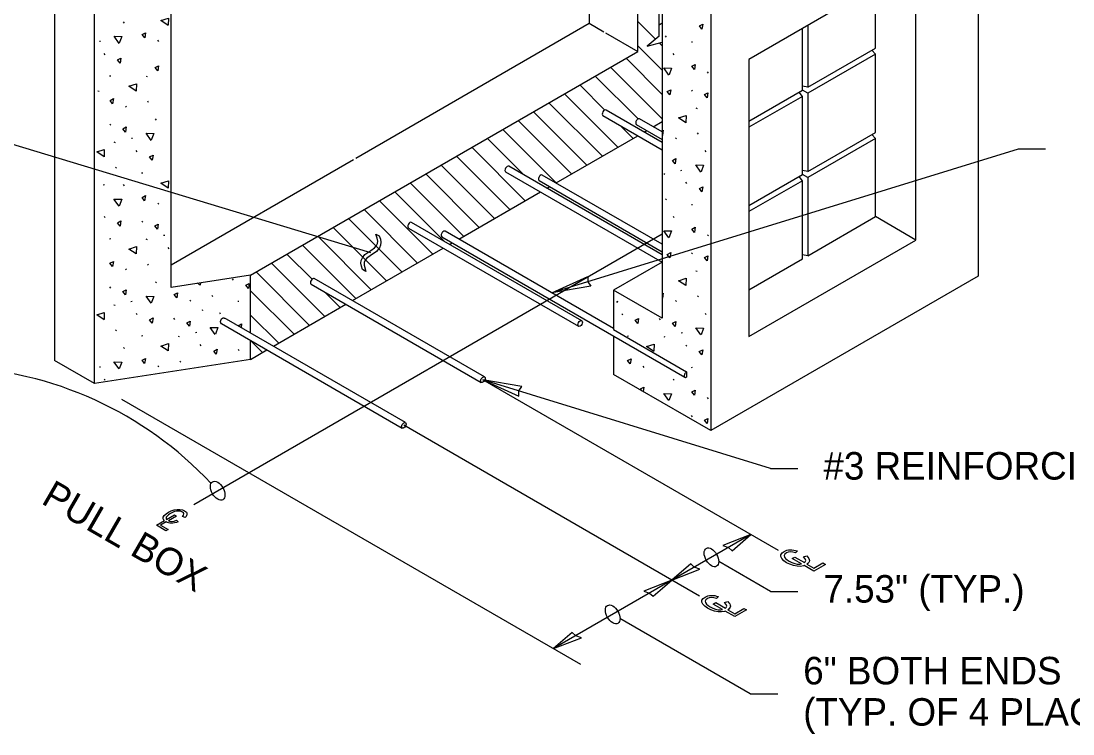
# Model space of a CAD drawing. Extents: x 99862 to 103151, y 100000 to 105076.
# Drawn here: x 100499 to 101110, y 104068 to 104482 of the extents above; entities that cross this region are included whole.
import ezdxf

# ---------------------------------------------------------------- set-up
doc = ezdxf.new("R2010")
doc.units = 0
for name, color, linetype in [('Level 14', 7, 'Continuous'), ('Level 15', 7, 'Continuous'), ('Level 2', 7, 'Continuous'), ('Level 20', 7, 'Continuous'), ('Level 9', 7, 'Continuous')]:
    doc.layers.add(name, color=color, linetype=linetype)

msp = doc.modelspace()

# ---------------------------------------------------------------- linework, layer by layer
at = {"layer": 'Level 14'}
for p, q in [((100871.55, 104411.82), (100838.9, 104430.67)), ((100837.03, 104427.42), (100871.55, 104407.49)), ((100871.55, 104417.94), (100858.35, 104425.57)), ((100856.47, 104422.32), (100871.55, 104413.61)), ((100780.46, 104394.76), (100871.45, 104342.23)), ((100871.55, 104346.5), (100782.33, 104398.01)), ((100799.9, 104389.66), (100871.55, 104348.29)), ((100871.55, 104352.63), (100801.78, 104392.91)), ((100824.76, 104308.2), (100725.77, 104365.35)), ((100723.89, 104362.1), (100822.89, 104304.95)), ((100743.34, 104357), (100884.76, 104275.35)), ((100843.27, 104303.64), (100745.21, 104360.25)), ((100768.19, 104275.54), (100669.2, 104332.69)), ((100667.32, 104329.44), (100766.32, 104272.29)), ((100722.23, 104249), (100618.09, 104309.13)), ((100615.13, 104306.51), (100720.36, 104245.75)), ((100843.27, 104303), (100885.7, 104278.51)), ((100885.7, 104278.51), (100885.7, 104275.44))]:
    msp.add_line(p, q, dxfattribs=at)
for centre, major_axis, start_param, end_param in [((100837.97, 104429.05), (-0.94, -1.62), 3.1416, 6.283185), ((100837.97, 104429.05), (-0.94, -1.62), 3.141593, 3.1416), ((100857.41, 104423.94), (-0.94, -1.62), 3.141593, 6.283191), ((100857.41, 104423.94), (-0.94, -1.62), 3.14158, 3.141593), ((100781.4, 104396.39), (-0.94, -1.62), 3.1416, 6.283185), ((100781.4, 104396.39), (-0.94, -1.62), 3.141593, 3.1416), ((100800.84, 104391.28), (0.94, 1.62), 6.283185, 9.424778), ((100724.83, 104363.73), (-0.94, -1.62), 3.1416, 6.283185), ((100724.83, 104363.73), (-0.94, -1.62), 3.141593, 3.1416), ((100744.27, 104358.62), (0.94, 1.62), 6.283185, 9.424778), ((100668.26, 104331.07), (-0.94, -1.62), 3.1416, 6.283185), ((100668.26, 104331.07), (-0.94, -1.62), 3.141593, 3.1416), ((100885.7, 104276.98), (0.94, 1.62), 0.785398, 3.926991)]:
    msp.add_ellipse(centre, major_axis=major_axis, ratio=0.57735, start_param=start_param, end_param=end_param, dxfattribs=at)
for centre, major_axis in [((100823.82, 104306.57), (-0.94, -1.62)), ((100767.25, 104273.91), (-0.94, -1.62)), ((100721.29, 104247.38), (0.94, 1.62))]:
    msp.add_ellipse(centre, major_axis=major_axis, ratio=0.57735, dxfattribs=at)
msp.add_open_spline([(100618.09, 104309.13), (100616.3, 104310.16), (100614.52, 104308.86), (100614.52, 104307.49), (100614.52, 104307.12), (100614.7, 104306.76), (100615.13, 104306.51)], degree=4, dxfattribs=at)
at = {"layer": 'Level 15'}
for p, q in [((100702.12, 104347.71), (100460.43, 104420.67)), ((101078.52, 104407.97), (100807.38, 104324.36)), ((101094.52, 104407.97), (101078.52, 104407.97)), ((100599.14, 104201.35), (100871.55, 104358.62)), ((100705.79, 104356.24), (100705.05, 104358.55)), ((100705.05, 104358.55), (100706.88, 104357.5)), ((100706.88, 104357.5), (100707.65, 104355.66)), ((100704.16, 104350.49), (100705.41, 104351.94)), ((100705.41, 104351.94), (100705.91, 104353.18)), ((100706.06, 104354.53), (100705.79, 104356.24)), ((100705.91, 104353.18), (100706.06, 104354.53)), ((100707.74, 104352.2), (100707.07, 104350.57)), ((100707.65, 104355.66), (100707.94, 104353.89)), ((100707.94, 104353.89), (100707.74, 104352.2)), ((100696.48, 104343.3), (100697.13, 104344.83)), ((100697.13, 104344.83), (100698.67, 104346.75)), ((100698.67, 104346.75), (100702.07, 104349.02)), ((100701.69, 104345.97), (100699.7, 104344.58)), ((100705.32, 104348.49), (100701.69, 104345.97)), ((100702.07, 104349.02), (100704.16, 104350.49)), ((100707.07, 104350.57), (100705.32, 104348.49)), ((100696.3, 104341.69), (100696.48, 104343.3)), ((100696.57, 104339.93), (100696.3, 104341.69)), ((100697.32, 104337.92), (100696.57, 104339.93)), ((100698.28, 104342.08), (100698.22, 104340.44)), ((100698.22, 104340.44), (100699.15, 104336.86)), ((100698.75, 104343.42), (100698.28, 104342.08)), ((100699.7, 104344.58), (100698.75, 104343.42)), ((100699.15, 104336.86), (100697.32, 104337.92)), ((100939.18, 104174.65), (100767.25, 104273.91)), ((100934.5, 104222.33), (100767.25, 104273.91)), ((100824.27, 104108.31), (100557.32, 104262.44)), ((100893.22, 104148.12), (100721.29, 104247.38)), ((100934.5, 104222.33), (100950.5, 104222.33)), ((100923.18, 104183.89), (100877.22, 104157.35)), ((100934.5, 104150.82), (100904.44, 104168.17)), ((100877.22, 104157.35), (100808.27, 104117.55)), ((100934.5, 104150.82), (100950.5, 104150.82)), ((100922.75, 104091.26), (100846.99, 104135)), ((100922.75, 104091.26), (100938.75, 104091.26))]:
    msp.add_line(p, q, dxfattribs=at)
for points in [[(100807.38, 104324.36), (100828.31, 104333.94), (100828.19, 104330.77), (100830.08, 104328.23)], [(100767.25, 104273.91), (100788.19, 104264.33), (100788.06, 104267.5), (100789.95, 104270.04)], [(100923.18, 104183.89), (100906.89, 104177.57), (100910.19, 104176.39), (100912.23, 104174.48)], [(100877.22, 104157.36), (100893.51, 104163.68), (100890.21, 104164.86), (100888.17, 104166.76)], [(100877.22, 104157.35), (100860.92, 104151.03), (100864.23, 104149.85), (100866.27, 104147.95)], [(100808.27, 104117.55), (100824.57, 104123.87), (100821.27, 104125.05), (100819.22, 104126.96)]]:
    msp.add_lwpolyline(points, close=True, dxfattribs=at)
msp.add_arc((100452.38, 104066.63), 214.86, 43.15406, 87.85248, dxfattribs=at)
for centre in [(100612.99, 104209.35), (100900.2, 104170.62), (100842.75, 104137.45)]:
    msp.add_ellipse(centre, major_axis=(-3, 5.2), ratio=0.57735, dxfattribs=at)
at = {"layer": 'Level 2'}
for p, q in [((101055.4, 104628.07), (101055.4, 104334.13)), ((100518, 104579.08), (100518, 104285.14)), ((100541.32, 104271.68), (100541.32, 104565.61)), ((100585.94, 104447.06), (100585.94, 104568.43)), ((101019.13, 104516.26), (100921.96, 104460.16)), ((101019.13, 104355.07), (101019.13, 104516.26)), ((100829.13, 104512.04), (100829.13, 104481.1)), ((100995.52, 104466.68), (100995.52, 104502.63)), ((100899.84, 104497.43), (100899.84, 104244.32)), ((100857.41, 104464.77), (100857.41, 104490.4)), ((100869.79, 104473.7), (100869.79, 104490.43)), ((100871.55, 104490.29), (100871.55, 104309.64)), ((100693.28, 104402.67), (100829.13, 104481.1)), ((100829.13, 104481.1), (100837.55, 104476.24)), ((100857.41, 104482.18), (100867.66, 104471.94)), ((100871.55, 104481.1), (100869.79, 104480.08)), ((100956.19, 104479.92), (100956.19, 104443.98)), ((100838.64, 104475.61), (100857.41, 104464.77)), ((100869.79, 104473.7), (100862.71, 104467.83)), ((100953.09, 104442.19), (100953.09, 104478.13)), ((100857.41, 104468.04), (100871.55, 104453.9)), ((100862.71, 104467.83), (100871.55, 104470.2)), ((100869.85, 104469.74), (100871.55, 104468.04)), ((100632.15, 104334.72), (100857.41, 104464.77)), ((100956.19, 104443.98), (100995.52, 104466.68)), ((100995.52, 104463.11), (100956.19, 104440.4)), ((100995.52, 104463.11), (100993.53, 104465.54)), ((100995.52, 104417.69), (100995.52, 104463.11)), ((100841.55, 104455.61), (100871.55, 104425.62)), ((100850.52, 104460.79), (100871.55, 104439.76)), ((100921.96, 104460.16), (100921.96, 104298.97)), ((100832.59, 104450.44), (100857.54, 104425.48)), ((100585.94, 104327.57), (100585.94, 104447.06)), ((100823.62, 104445.26), (100838.22, 104430.66)), ((100956.19, 104443.98), (100953.09, 104444.48)), ((100814.66, 104440.09), (100845.72, 104409.03)), ((100921.96, 104424.22), (100953.09, 104442.19)), ((100953.09, 104438.61), (100921.96, 104420.64)), ((100953.09, 104438.61), (100951.11, 104441.04)), ((100956.19, 104440.4), (100953.09, 104442.19)), ((100953.09, 104393.2), (100953.09, 104438.61)), ((100956.19, 104440.4), (100956.19, 104394.99)), ((100805.69, 104434.91), (100836.75, 104403.85)), ((100787.76, 104424.56), (100818.82, 104393.5)), ((100796.73, 104429.73), (100827.78, 104398.67)), ((100778.79, 104419.38), (100809.85, 104388.32)), ((100847.52, 104421.37), (100854.68, 104414.2)), ((100861.05, 104417.88), (100862.61, 104418.78)), ((100866.36, 104420.94), (100871.55, 104423.94)), ((100769.83, 104414.2), (100791.05, 104392.98)), ((100809.79, 104388.28), (100857.3, 104415.72)), ((100956.19, 104394.99), (100995.52, 104417.69)), ((100995.52, 104414.12), (100956.19, 104391.41)), ((100995.52, 104414.12), (100993.53, 104416.55)), ((100995.52, 104368.7), (100995.52, 104414.12)), ((100760.86, 104409.03), (100791.92, 104377.97)), ((100585.94, 104340.69), (100692.06, 104401.97)), ((100751.9, 104403.85), (100782.95, 104372.79)), ((100742.93, 104398.67), (100773.99, 104367.62)), ((100956.19, 104394.99), (100953.09, 104395.49)), ((100725, 104388.32), (100756.06, 104357.26)), ((100733.97, 104393.5), (100765.02, 104362.44)), ((100921.96, 104375.23), (100953.09, 104393.2)), ((100953.09, 104389.62), (100921.96, 104371.65)), ((100953.09, 104389.62), (100951.11, 104392.05)), ((100956.19, 104391.41), (100953.09, 104393.2)), ((100953.09, 104344.21), (100953.09, 104389.62)), ((100956.19, 104391.41), (100956.19, 104346)), ((100716.03, 104383.15), (100744.84, 104354.34)), ((100753.22, 104355.63), (100800.74, 104383.06)), ((100804.49, 104385.22), (100806.04, 104386.12)), ((100707.07, 104377.97), (100738.13, 104346.91)), ((100698.1, 104372.79), (100729.16, 104341.73)), ((100689.14, 104367.62), (100720.19, 104336.56)), ((100956.19, 104346), (100995.52, 104368.7)), ((101019.13, 104355.07), (100995.52, 104368.7)), ((100671.2, 104357.26), (100702.26, 104326.21)), ((100680.17, 104362.44), (100711.23, 104331.38)), ((100662.24, 104352.09), (100693.3, 104321.03)), ((100747.92, 104352.56), (100749.47, 104353.46)), ((100921.96, 104298.97), (101019.13, 104355.07)), ((100653.27, 104346.91), (100667.9, 104332.29)), ((100691.35, 104319.9), (100744.17, 104350.4)), ((100956.19, 104346), (100953.09, 104346.5)), ((100644.31, 104341.73), (100675.37, 104310.68)), ((100871.55, 104342.3), (100843.27, 104325.97)), ((100921.96, 104326.24), (100953.09, 104344.21)), ((100632.15, 104334.72), (100585.94, 104327.57)), ((100632.15, 104301.01), (100632.15, 104334.72)), ((100635.34, 104336.56), (100666.4, 104305.5)), ((101055.4, 104334.13), (100899.84, 104244.32)), ((100632.15, 104325.61), (100657.43, 104300.32)), ((100675.41, 104324.78), (100684.33, 104315.85)), ((100843.27, 104325.97), (100843.27, 104303)), ((100871.55, 104309.64), (100843.27, 104325.97)), ((100645.39, 104293.37), (100687.6, 104317.74)), ((100632.15, 104311.46), (100648.47, 104295.15)), ((100632.15, 104285.73), (100632.15, 104296.68)), ((100632.36, 104296.56), (100639.15, 104289.77)), ((100843.27, 104299.31), (100843.27, 104276.98)), ((100632.15, 104285.73), (100641.64, 104291.2)), ((100541.32, 104271.68), (100518, 104285.14)), ((100632.15, 104285.73), (100541.32, 104271.68)), ((100899.84, 104244.32), (100843.27, 104276.98))]:
    msp.add_line(p, q, dxfattribs=at)
at = {"layer": 'Level 20'}
for points in [[(100594.12, 104193.85), (100592.57, 104194.38), (100593.18, 104195.14), (100593.4, 104195.85), (100593.13, 104196.45), (100592.52, 104196.93), (100591.46, 104197.4), (100590.31, 104197.55), (100589.05, 104197.47), (100587.82, 104197.18), (100586.64, 104196.74), (100585.51, 104196.17), (100584.35, 104195.42), (100583.53, 104194.65), (100583.03, 104193.89), (100583, 104193.17), (100583.26, 104192.7), (100587.83, 104195.35), (100589.06, 104194.64), (100584.36, 104191.92), (100585.01, 104191.67), (100586.25, 104191.54), (100587.64, 104191.71), (100589.14, 104192.18), (100590.01, 104191.28), (100588.95, 104190.92), (100587.96, 104190.69), (100586.96, 104190.55), (100586.1, 104190.5), (100585.17, 104190.56), (100584.34, 104190.72), (100583.57, 104190.97), (100583.11, 104191.2), (100579.76, 104189.25), (100584.14, 104186.73), (100582.92, 104186.03), (100577.32, 104189.27), (100582, 104191.97), (100581.75, 104192.15), (100581.26, 104193.04), (100581.33, 104193.97), (100581.93, 104194.97), (100582.95, 104195.96), (100584.3, 104196.87), (100585.96, 104197.69), (100587.69, 104198.24), (100589.4, 104198.5), (100591.03, 104198.46), (100592.51, 104198.16), (100593.78, 104197.62), (100594.35, 104197.23), (100594.77, 104196.81), (100595.03, 104196.36), (100595.15, 104195.88), (100595.12, 104195.39), (100594.93, 104194.89), (100594.59, 104194.37)], [(100950.21, 104174.31), (100949.12, 104173.23), (100947.52, 104173.66), (100946.11, 104173.8), (100944.87, 104173.63), (100943.78, 104173.18), (100942.88, 104172.47), (100942.52, 104171.65), (100942.67, 104170.8), (100943.29, 104169.93), (100944.24, 104169.11), (100945.4, 104168.35), (100947, 104167.54), (100948.59, 104166.95), (100950.12, 104166.62), (100951.56, 104166.6), (100952.6, 104166.78), (100947.12, 104169.94), (100948.59, 104170.79), (100954.22, 104167.54), (100954.75, 104167.99), (100955.01, 104168.84), (100954.67, 104169.8), (100953.68, 104170.85), (100955.57, 104171.45), (100956.28, 104170.73), (100956.79, 104170.04), (100957.08, 104169.37), (100957.16, 104168.72), (100957.04, 104168.1), (100956.73, 104167.53), (100956.21, 104166.99), (100955.73, 104166.67), (100959.75, 104164.35), (100965, 104167.38), (100966.46, 104166.54), (100959.73, 104162.66), (100954.12, 104165.9), (100953.74, 104165.74), (100951.9, 104165.39), (100949.95, 104165.44), (100947.88, 104165.86), (100945.82, 104166.56), (100943.92, 104167.5), (100942.23, 104168.66), (100941.1, 104169.85), (100940.56, 104171.03), (100940.63, 104172.17), (100941.26, 104173.2), (100942.39, 104174.07), (100943.21, 104174.46), (100944.08, 104174.75), (100945.01, 104174.94), (100945.99, 104175.02), (100947.02, 104175), (100948.06, 104174.87), (100949.13, 104174.64)], [(100904.25, 104147.78), (100903.17, 104146.7), (100901.57, 104147.14), (100900.15, 104147.27), (100898.92, 104147.11), (100897.82, 104146.66), (100896.92, 104145.94), (100896.56, 104145.13), (100896.71, 104144.27), (100897.34, 104143.41), (100898.29, 104142.58), (100899.44, 104141.82), (100901.05, 104141.01), (100902.63, 104140.43), (100904.17, 104140.1), (100905.61, 104140.07), (100906.64, 104140.26), (100901.16, 104143.42), (100902.64, 104144.27), (100908.27, 104141.01), (100908.79, 104141.47), (100909.06, 104142.32), (100908.71, 104143.28), (100907.73, 104144.32), (100909.62, 104144.93), (100910.33, 104144.21), (100910.83, 104143.52), (100911.12, 104142.85), (100911.21, 104142.2), (100911.09, 104141.58), (100910.77, 104141), (100910.25, 104140.47), (100909.78, 104140.14), (100913.79, 104137.82), (100919.04, 104140.86), (100920.5, 104140.02), (100913.78, 104136.14), (100908.16, 104139.38), (100907.78, 104139.21), (100905.95, 104138.87), (100903.99, 104138.92), (100901.93, 104139.33), (100899.87, 104140.04), (100897.97, 104140.98), (100896.28, 104142.14), (100895.14, 104143.33), (100894.6, 104144.51), (100894.67, 104145.64), (100895.31, 104146.67), (100896.44, 104147.54), (100897.25, 104147.94), (100898.12, 104148.23), (100899.06, 104148.42), (100900.04, 104148.5), (100901.07, 104148.47), (100902.11, 104148.34), (100903.17, 104148.11)]]:
    msp.add_lwpolyline(points, close=True, dxfattribs=at)
at = {"layer": 'Level 9'}
for p, q in [((100558.82, 104481.28), (100558.25, 104481.95)), ((100873.95, 104473.1), (100873.39, 104473.77)), ((100544.28, 104470.68), (100544.91, 104470.77)), ((100578.7, 104470.59), (100578.14, 104471.26)), ((100888.52, 104470.34), (100889.16, 104470.43)), ((100547.56, 104462.86), (100547, 104463.53)), ((100878.55, 104462.86), (100877.99, 104463.53)), ((100550.14, 104450.53), (100550.78, 104450.62)), ((100571.31, 104450.36), (100572.07, 104450.09)), ((100898.43, 104452.17), (100897.87, 104452.84)), ((100543.28, 104441.85), (100544.03, 104441.58)), ((100889.24, 104441.64), (100888.68, 104442.31)), ((100560.05, 104432.36), (100559.49, 104433.03)), ((100572.85, 104435.11), (100572.29, 104435.78)), ((100891.04, 104431.94), (100891.8, 104431.67)), ((100577.45, 104424.86), (100576.89, 104425.53)), ((100550.86, 104421.82), (100550.3, 104422.49)), ((100552.67, 104412.13), (100553.42, 104411.85)), ((100562.91, 104414.27), (100563.55, 104414.35)), ((100879.78, 104413.94), (100879.22, 104414.61)), ((100892.59, 104416.69), (100892.02, 104417.36)), ((100566.2, 104406.44), (100565.63, 104407.11)), ((100897.18, 104406.44), (100896.62, 104407.11)), ((100541.41, 104394.13), (100541.32, 104394.23)), ((100554.21, 104396.87), (100553.64, 104397.54)), ((100568.78, 104394.11), (100569.41, 104394.2)), ((100872.4, 104393.7), (100873.15, 104393.43)), ((100882.31, 104395.61), (100882.94, 104395.7)), ((100885.93, 104388.02), (100885.36, 104388.69)), ((100546.44, 104387.25), (100547.08, 104387.33)), ((100558.8, 104386.63), (100558.24, 104387.3)), ((100578.69, 104375.94), (100578.13, 104376.61)), ((100873.94, 104378.45), (100873.38, 104379.12)), ((100888.51, 104375.69), (100889.15, 104375.78)), ((100547.55, 104368.21), (100546.99, 104368.88)), ((100569.5, 104365.41), (100568.94, 104366.08)), ((100878.54, 104368.21), (100877.97, 104368.88)), ((100581.55, 104357.85), (100582.18, 104357.93)), ((100898.42, 104357.52), (100897.86, 104358.19)), ((100550.13, 104355.88), (100550.77, 104355.97)), ((100571.3, 104355.71), (100572.06, 104355.44)), ((100584.83, 104350.02), (100584.27, 104350.69)), ((100889.23, 104346.99), (100888.67, 104347.66)), ((100572.84, 104340.46), (100572.28, 104341.13)), ((100560.04, 104337.71), (100559.48, 104338.38)), ((100622.11, 104331.84), (100621.55, 104332.51)), ((100891.03, 104337.29), (100891.79, 104337.02)), ((100550.85, 104327.17), (100550.29, 104327.84)), ((100577.44, 104330.21), (100576.88, 104330.88)), ((100610.13, 104322.27), (100609.56, 104322.94)), ((100892.57, 104322.04), (100892.01, 104322.71)), ((100552.65, 104317.48), (100553.41, 104317.21)), ((100562.56, 104319.39), (100563.2, 104319.47)), ((100597.32, 104319.53), (100596.76, 104320.2)), ((100604.02, 104314.42), (100604.65, 104314.51)), ((100624.7, 104319.51), (100625.33, 104319.6)), ((100845.01, 104319.15), (100845.65, 104319.24)), ((100845.35, 104319.38), (100845.99, 104319.47)), ((100879.77, 104319.29), (100879.21, 104319.96)), ((100566.18, 104311.79), (100565.62, 104312.46)), ((100588.14, 104308.99), (100587.57, 104309.66)), ((100614.72, 104312.03), (100614.16, 104312.7)), ((100848.63, 104311.55), (100848.07, 104312.22)), ((100870.58, 104308.75), (100870.02, 104309.42)), ((100897.17, 104311.79), (100896.61, 104312.46)), ((100554.19, 104302.23), (100553.63, 104302.9)), ((100541.39, 104299.48), (100541.32, 104299.56)), ((100568.77, 104299.46), (100569.4, 104299.55)), ((100589.94, 104299.29), (100590.69, 104299.02)), ((100600.19, 104301.43), (100600.82, 104301.52)), ((100851.22, 104299.23), (100851.85, 104299.31)), ((100872.39, 104299.06), (100873.14, 104298.79)), ((100882.63, 104301.2), (100883.27, 104301.28)), ((100558.79, 104291.98), (100558.23, 104292.65)), ((100603.47, 104293.61), (100602.9, 104294.28)), ((100625.42, 104290.81), (100624.86, 104291.48)), ((100885.92, 104293.37), (100885.35, 104294.04)), ((100591.48, 104284.04), (100590.92, 104284.71)), ((100544.26, 104281.38), (100544.89, 104281.47)), ((100578.68, 104281.29), (100578.11, 104281.96)), ((100861.13, 104281.06), (100860.56, 104281.73)), ((100888.5, 104281.04), (100889.13, 104281.13)), ((100547.54, 104273.56), (100546.97, 104274.23)), ((100878.53, 104273.56), (100877.96, 104274.23)), ((100898.41, 104262.87), (100897.85, 104263.54)), ((100889.22, 104252.34), (100888.66, 104253.01))]:
    msp.add_line(p, q, dxfattribs=at)
for points in [[(100584.26, 104479.9), (100580.01, 104482.76), (100584.35, 104484.18), (100584.27, 104479.99)], [(100894.68, 104477.71), (100893.16, 104479.64), (100895.13, 104480.65), (100894.68, 104477.71)], [(100555.72, 104469.45), (100552.7, 104473.59), (100557.26, 104473.44), (100555.75, 104469.53)], [(100570.54, 104472.61), (100569.02, 104474.54), (100570.99, 104475.56), (100570.54, 104472.61)], [(100556.31, 104457.9), (100554.78, 104459.83), (100556.75, 104460.84), (100556.31, 104457.9)], [(100578.22, 104453.4), (100576.69, 104455.33), (100578.67, 104456.35), (100578.22, 104453.4)], [(100875.45, 104451.03), (100872.43, 104455.17), (100877, 104455.02), (100875.49, 104451.11)], [(100890.28, 104454.19), (100888.75, 104456.12), (100890.72, 104457.14), (100890.28, 104454.19)], [(100565.61, 104441.67), (100561.36, 104444.52), (100565.71, 104445.94), (100565.62, 104441.75)], [(100551.9, 104434.38), (100550.37, 104436.31), (100552.34, 104437.32), (100551.9, 104434.38)], [(100876.04, 104439.48), (100874.51, 104441.41), (100876.49, 104442.42), (100876.04, 104439.48)], [(100897.7, 104437.71), (100896.17, 104439.64), (100898.15, 104440.65), (100897.7, 104437.71)], [(100885.35, 104423.25), (100881.09, 104426.1), (100885.44, 104427.52), (100885.36, 104423.33)], [(100559.32, 104417.9), (100557.79, 104419.83), (100559.77, 104420.84), (100559.32, 104417.9)], [(100871.55, 104418.63), (100872.08, 104418.9), (100871.63, 104415.96)], [(100574.35, 104413.04), (100571.33, 104417.18), (100575.9, 104417.02), (100574.39, 104413.12)], [(100871.63, 104415.96), (100871.55, 104416.06)], [(100546.97, 104403.43), (100542.71, 104406.29), (100547.06, 104407.71), (100546.98, 104403.52)], [(100574.94, 104401.48), (100573.41, 104403.41), (100575.39, 104404.43), (100574.94, 104401.48)], [(100879.05, 104399.48), (100877.53, 104401.41), (100879.5, 104402.42), (100879.05, 104399.48)], [(100894.08, 104394.61), (100891.06, 104398.76), (100895.63, 104398.6), (100894.12, 104394.69)], [(100584.25, 104385.25), (100580, 104388.11), (100584.34, 104389.53), (100584.26, 104385.34)], [(100894.67, 104383.06), (100893.15, 104384.99), (100895.12, 104386.01), (100894.67, 104383.06)], [(100555.7, 104374.8), (100552.69, 104378.94), (100557.25, 104378.79), (100555.74, 104374.88)], [(100570.53, 104377.96), (100569.01, 104379.89), (100570.98, 104380.91), (100570.53, 104377.96)], [(100556.29, 104363.25), (100554.77, 104365.18), (100556.74, 104366.19), (100556.29, 104363.25)], [(100577.96, 104361.48), (100576.43, 104363.41), (100578.41, 104364.42), (100577.96, 104361.48)], [(100875.44, 104356.38), (100872.42, 104360.52), (100876.99, 104360.37), (100875.48, 104356.46)], [(100890.27, 104359.54), (100888.74, 104361.47), (100890.71, 104362.49), (100890.27, 104359.54)], [(100565.6, 104347.02), (100561.35, 104349.88), (100565.7, 104351.29), (100565.61, 104347.11)], [(100876.03, 104344.83), (100874.5, 104346.76), (100876.47, 104347.77), (100876.03, 104344.83)], [(100897.69, 104343.06), (100896.16, 104344.99), (100898.14, 104346), (100897.69, 104343.06)], [(100551.89, 104339.73), (100550.36, 104341.66), (100552.33, 104342.67), (100551.89, 104339.73)], [(100885.34, 104328.6), (100881.08, 104331.45), (100885.43, 104332.87), (100885.34, 104328.69)], [(100602.89, 104328.83), (100601.25, 104329.94)], [(100602.92, 104330.19), (100602.9, 104328.92)], [(100630.86, 104326.88), (100629.33, 104328.81), (100631.31, 104329.82), (100630.86, 104326.88)], [(100559.31, 104323.25), (100557.78, 104325.18), (100559.76, 104326.19), (100559.31, 104323.25)], [(100574.34, 104318.39), (100571.32, 104322.53), (100575.89, 104322.37), (100574.38, 104318.47)], [(100589.17, 104321.55), (100587.64, 104323.48), (100589.62, 104324.49), (100589.17, 104321.55)], [(100871.55, 104323.99), (100872.07, 104324.25), (100871.62, 104321.31)], [(100871.62, 104321.31), (100871.55, 104321.39)], [(100856.79, 104318.15), (100856.78, 104318.17)], [(100546.96, 104308.79), (100542.7, 104311.64), (100547.05, 104313.06), (100546.97, 104308.87)], [(100574.93, 104306.83), (100573.4, 104308.76), (100575.38, 104309.78), (100574.93, 104306.83)], [(100596.59, 104305.06), (100595.07, 104306.99), (100597.04, 104308.01), (100596.59, 104305.06)], [(100857.38, 104306.6), (100855.85, 104308.53), (100857.83, 104309.54), (100857.38, 104306.6)], [(100611.62, 104300.2), (100608.6, 104304.34), (100613.17, 104304.19), (100611.66, 104300.28)], [(100625.09, 104305.09), (100624.92, 104305.29), (100626.9, 104306.31), (100626.58, 104304.22)], [(100879.04, 104304.83), (100877.51, 104306.76), (100879.49, 104307.77), (100879.04, 104304.83)], [(100894.07, 104299.97), (100891.05, 104304.11), (100895.62, 104303.95), (100894.11, 104300.05)], [(100584.24, 104290.6), (100579.99, 104293.46), (100584.33, 104294.88), (100584.25, 104290.69)], [(100612.21, 104288.65), (100610.69, 104290.58), (100612.66, 104291.59), (100612.21, 104288.65)], [(100866.69, 104290.36), (100862.43, 104293.22), (100866.78, 104294.64), (100866.7, 104290.45)], [(100894.66, 104288.41), (100893.13, 104290.34), (100895.11, 104291.36), (100894.66, 104288.41)], [(100555.69, 104280.15), (100552.67, 104284.29), (100557.24, 104284.14), (100555.73, 104280.23)], [(100570.52, 104283.31), (100568.99, 104285.25), (100570.97, 104286.26), (100570.52, 104283.31)], [(100852.97, 104283.08), (100851.44, 104285.01), (100853.42, 104286.02), (100852.97, 104283.08)], [(100859.68, 104267.5), (100858.87, 104268.53), (100860.84, 104269.54), (100860.46, 104267.05)], [(100875.43, 104261.73), (100872.41, 104265.87), (100876.97, 104265.72), (100875.46, 104261.81)], [(100890.25, 104264.89), (100888.73, 104266.83), (100890.7, 104267.84), (100890.25, 104264.89)], [(100897.68, 104248.41), (100896.15, 104250.34), (100898.13, 104251.35), (100897.68, 104248.41)]]:
    msp.add_lwpolyline(points, dxfattribs=at)

# ---------------------------------------------------------------- texts
at = {"layer": 'Level 20'}
for s, p in [('#3 REINFORCING BAR (TYP.)', (100965.31, 104215.82)), ('7.53" (TYP.)', (100965.31, 104144.3)), ('6" BOTH ENDS', (100953.55, 104096.75)), ('(TYP. OF 4 PLACES)', (100953.55, 104072.75))]:
    msp.add_text(s, height=16, dxfattribs=at).set_placement(p)
msp.add_text('PULL BOX', height=16, rotation=330.02711, dxfattribs=at).set_placement((100509.73, 104202.26))

doc.saveas('drawing.dxf')
